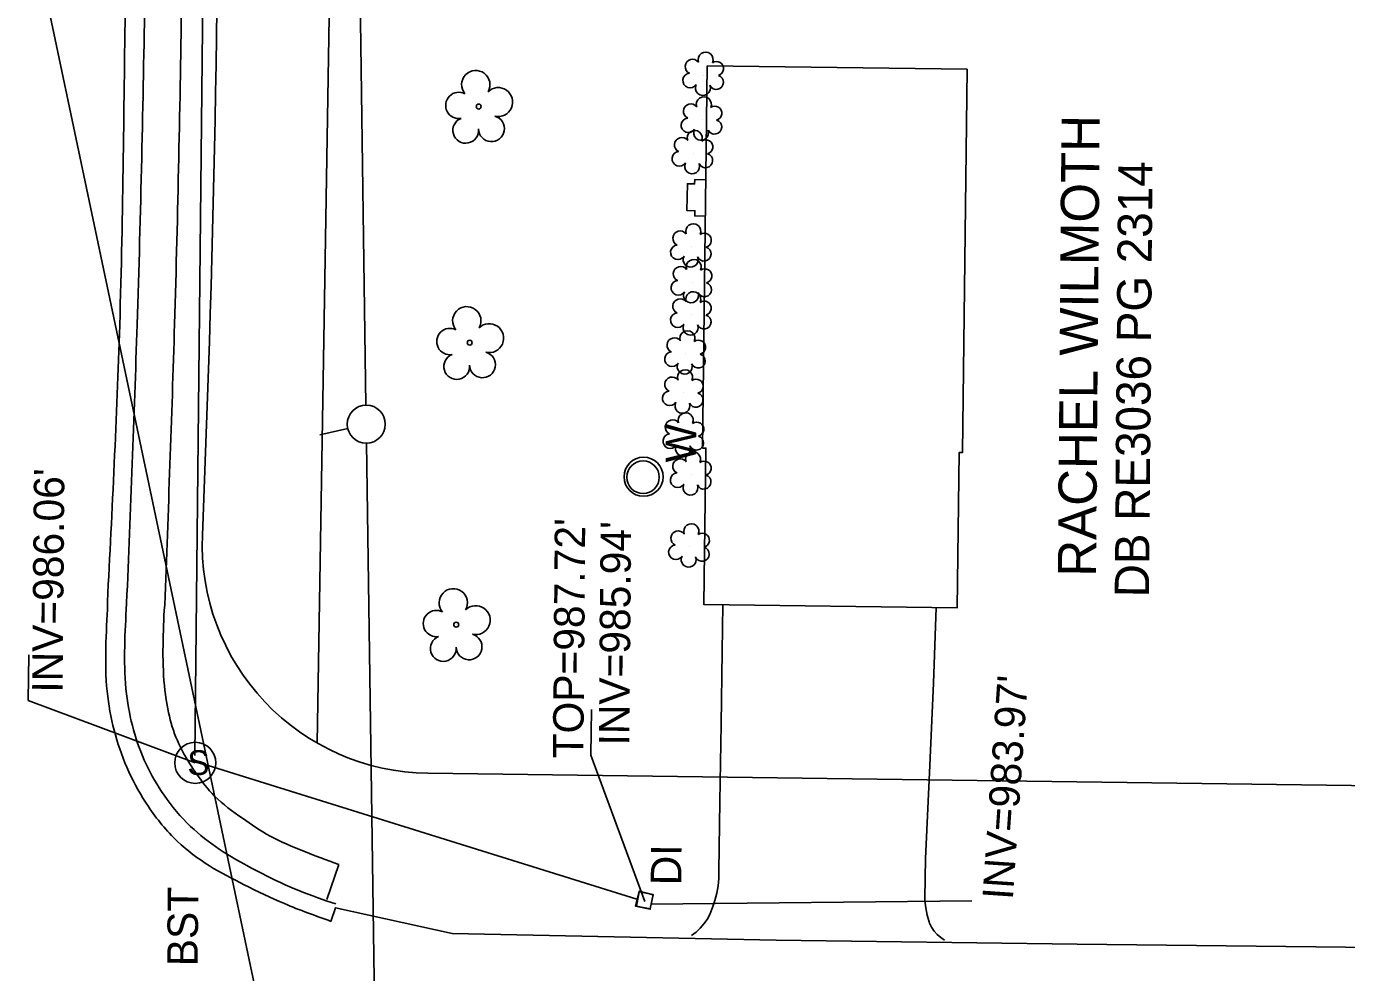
# Model space of a CAD drawing. Extents: x 1611576 to 1617186, y 899279 to 905462.
# Drawn here: x 1616695.8 to 1616869, y 902069.8 to 902193.9 of the extents above; entities that cross this region are included whole.
import ezdxf

# ---------------------------------------------------------------- set-up
doc = ezdxf.new("R2010")
doc.units = 0
for name, color, linetype in [('Default', 7, 'Continuous'), ('Exist Building', 7, 'Continuous'), ('Exist Other Culture Area Outline', 7, 'Continuous'), ('Exist Other Culture Well CELL', 7, 'Continuous'), ('Exist Other Culture Well Text', 7, 'Continuous'), ('Exist Property Deed Book Text', 7, 'Continuous'), ('Exist Property Owner Text', 7, 'Continuous'), ('Exist Right of Way Easement Line', 7, 'Continuous'), ('Exist Right of Way Line', 7, 'Continuous'), ('Exist Roads Curbs', 7, 'Continuous'), ('Exist Roads EOP', 7, 'Continuous'), ('Exist Roads EOP Other', 7, 'Continuous'), ('Exist Roads EOP Text', 7, 'Continuous'), ('Exist Structure Minor Drop Inlet', 7, 'Continuous'), ('Exist Structure Minor Drop Inlet Leader', 7, 'Continuous'), ('Exist Structure Minor Drop Inlet Text', 7, 'Continuous'), ('Exist Structure Minor Drop Inlet Top Elevation', 7, 'Continuous'), ('Exist Structure Minor Pipes RCP 12 Inch', 7, 'Continuous'), ('Exist Structure Minor Pipes RCP 12 Inch Invert', 7, 'Continuous'), ('Exist Structure Minor Pipes RCP 15 Inch', 7, 'Continuous'), ('Exist Structure Minor Pipes RCP 15 Inch Invert', 7, 'Continuous'), ('Exist Structure Minor Storm Sewer Manhole CELL', 7, 'Continuous'), ('Exist Structure Minor Storm Sewer Manhole Leader', 7, 'Continuous'), ('Exist Vegetation Shrub CELL', 7, 'Continuous'), ('Exist Vegetation Tree CELL', 7, 'Continuous'), ('Prop OH Pow Lines', 7, 'Continuous')]:
    doc.layers.add(name, color=color, linetype=linetype)

# ---------------------------------------------------------------- blocks, each defined once
blk = doc.blocks.new('EXIST STRUCTURE MINOR STORM SEWER MANHOLE')
at = {"layer": 'Exist Structure Minor Storm Sewer Manhole CELL'}
blk.add_circle((0, 0), 0.0539, dxfattribs=at)
blk.add_text('S', height=0.065, dxfattribs=at).set_placement((-0.0206, -0.032))
blk = doc.blocks.new('EXIST OTHER CULTURE WELL')
at = {"layer": 'Exist Other Culture Well CELL'}
blk.add_circle((0.0001, 0.0001), 0.0512, dxfattribs=at)

msp = doc.modelspace()

# ---------------------------------------------------------------- linework, layer by layer
at = {"layer": 'Default'}
msp.add_line((1616737.91, 902141.2), (1616734.25, 902140.36), dxfattribs=at)
msp.add_circle((1616740.35, 902141.76), 2.5, dxfattribs=at)
at = {"layer": 'Exist Building'}
msp.add_lwpolyline([(1616819.19, 902188.32), (1616818.57, 902138.04), (1616818.13, 902138.04), (1616817.88, 902117.69), (1616784.65, 902118.1), (1616784.91, 902138.63), (1616784.47, 902138.63), (1616785.09, 902188.74)], close=True, dxfattribs=at)
at = {"layer": 'Exist Other Culture Area Outline'}
msp.add_lwpolyline([(1616784.84, 902169.04), (1616783.44, 902169.08), (1616783.46, 902169.75), (1616782.41, 902169.77), (1616782.49, 902173.3), (1616783.43, 902173.28), (1616783.44, 902173.85), (1616784.9, 902173.82)], dxfattribs=at)
at = {"layer": 'Exist Other Culture Well CELL'}
msp.add_circle((1616776.73, 902134.86), 2.56, dxfattribs=at)
at = {"layer": 'Exist Right of Way Easement Line'}
msp.add_line((1616733.92, 902099.93), (1616735.65, 902205.83), dxfattribs=at)
at = {"layer": 'Exist Right of Way Line'}
for p, q in [((1616010.65, 905462.23), (1616993.32, 900797.76)), ((1616748.43, 902095.97), (1616995.9, 902092.72))]:
    msp.add_line(p, q, dxfattribs=at)
for centre, radius, start, end in [((1614235.45, 902230.14), 2485.53, 357.62671, 2.98333), ((1616748.82, 902125.97), 30, 177.6267, 269.2466)]:
    msp.add_arc(centre, radius, start, end, dxfattribs=at)
at = {"layer": 'Exist Roads Curbs'}
for p, q in [((1616708.91, 902118.28), (1616708.86, 902117.45)), ((1616735.21, 902079.21), (1616736.35, 902078.85))]:
    msp.add_line(p, q, dxfattribs=at)
for points in [[(1616711.07, 902282.06), (1616711.54, 902240.78), (1616711.3, 902198.45), (1616710.29, 902154.83), (1616708.91, 902118.28)], [(1616708.86, 902117.45), (1616708.9, 902106.37), (1616711.47, 902097.16), (1616713.82, 902093.09), (1616717.31, 902088.99), (1616721.06, 902086.03), (1616725.48, 902083.44), (1616730.31, 902081.08), (1616735.21, 902079.21)]]:
    msp.add_spline(points, degree=3, dxfattribs=at)
at = {"layer": 'Exist Roads EOP'}
msp.add_line((1616706.39, 902118.44), (1616706.4, 902117.47), dxfattribs=at)
msp.add_lwpolyline([(1616735.72, 902076.55), (1616736.31, 902078.34), (1616751.61, 902074.96), (1616794.12, 902074.08), (1616833.63, 902073.55), (1616876.66, 902073.09), (1616919.02, 902072.24), (1616961.16, 902071.7), (1616995.87, 902071.17)], dxfattribs=at)
for points in [[(1616700.66, 902435.94), (1616702.18, 902418.73), (1616703.04, 902404.79), (1616704.57, 902383.66), (1616705.67, 902361.58), (1616706.31, 902348.15), (1616707.03, 902335.33), (1616707.82, 902320.47), (1616708.2, 902308.47), (1616708.4, 902295.6), (1616708.73, 902282.72), (1616709.32, 902240.78), (1616708.76, 902198.62), (1616708, 902154.76), (1616706.39, 902118.44)], [(1616706.4, 902117.47), (1616706.43, 902106.02), (1616709.2, 902096.18), (1616711.76, 902091.62), (1616715.59, 902087.04), (1616719.77, 902083.84), (1616724.34, 902081.35), (1616729.62, 902078.87), (1616735.72, 902076.55)]]:
    msp.add_spline(points, degree=3, dxfattribs=at)
at = {"layer": 'Exist Roads EOP Other'}
for p, q in [((1616713.91, 902118.06), (1616713.83, 902117.33)), ((1616736.74, 902084), (1616735.16, 902079.4))]:
    msp.add_line(p, q, dxfattribs=at)
for points in [[(1616783.04, 902074.7), (1616783.63, 902075.14), (1616784.17, 902075.65), (1616784.65, 902076.21), (1616785.07, 902076.81), (1616785.42, 902077.46), (1616785.7, 902078.15), (1616785.77, 902078.38), (1616786.1, 902079.3), (1616786.34, 902080.25), (1616786.51, 902081.22), (1616786.6, 902082.19), (1616786.61, 902083.17), (1616786.61, 902083.19), (1616786.75, 902092.29), (1616786.9, 902102.43), (1616787.03, 902111.95), (1616787.12, 902118.07)], [(1616816.21, 902074.1), (1616815.71, 902074.43), (1616815.26, 902074.82), (1616814.86, 902075.27), (1616814.52, 902075.77), (1616814.26, 902076.31), (1616814.19, 902076.47), (1616813.93, 902077.38), (1616813.75, 902078.32), (1616813.64, 902079.26), (1616813.62, 902079.61), (1616813.74, 902084.78), (1616814.25, 902096.04), (1616814.76, 902107.81), (1616815.1, 902117.72)]]:
    msp.add_lwpolyline(points, dxfattribs=at)
for points in [[(1616716.14, 902275.65), (1616716.52, 902240.91), (1616716.15, 902198.42), (1616715.2, 902154.87), (1616713.91, 902118.06)], [(1616713.83, 902117.33), (1616713.94, 902106.82), (1616715.96, 902099.38), (1616718.02, 902095.99), (1616720.46, 902092.98), (1616724.09, 902090.07), (1616727.73, 902087.73), (1616732.03, 902085.79), (1616736.74, 902084)]]:
    msp.add_spline(points, degree=3, dxfattribs=at)
at = {"layer": 'Exist Structure Minor Drop Inlet'}
msp.add_lwpolyline([(1616777.99, 902080.01), (1616777.59, 902078.19), (1616777.61, 902078.13), (1616775.69, 902078.54), (1616776.15, 902080.49), (1616777.99, 902080.01)], dxfattribs=at)
msp.add_lwpolyline([(1616777.61, 902078.18), (1616775.81, 902078.52), (1616776.17, 902080.42), (1616777.97, 902080.08)], close=True, dxfattribs=at)
at = {"layer": 'Exist Structure Minor Drop Inlet Leader'}
msp.add_lwpolyline([(1616776.88, 902079.16), (1616769.83, 902098.35), (1616769.88, 902104.35)], dxfattribs=at)
at = {"layer": 'Exist Structure Minor Pipes RCP 12 Inch'}
msp.add_line((1616819.8, 902079.23), (1616777.68, 902078.8), dxfattribs=at)
at = {"layer": 'Exist Structure Minor Pipes RCP 15 Inch'}
for p, q in [((1616720.08, 902307.67), (1616717.86, 902098.31)), ((1616720.08, 902307.67), (1616717.86, 902098.31)), ((1616775.83, 902079.48), (1616718.9, 902097.22))]:
    msp.add_line(p, q, dxfattribs=at)
at = {"layer": 'Exist Structure Minor Storm Sewer Manhole Leader'}
msp.add_lwpolyline([(1616717.91, 902097.34), (1616696.01, 902105.52), (1616696.06, 902111.52)], dxfattribs=at)
at = {"layer": 'Exist Vegetation Shrub CELL'}
for p, q in [((1616784.64, 902187.53), (1616784.64, 902187.53)), ((1616784.41, 902181.67), (1616784.41, 902181.67)), ((1616783.22, 902177.26), (1616783.22, 902177.26)), ((1616783.03, 902165.01), (1616783.03, 902165.01)), ((1616783.09, 902160.34), (1616783.09, 902160.34)), ((1616783.02, 902156.11), (1616783.02, 902156.11)), ((1616782.26, 902150.99), (1616782.26, 902150.99)), ((1616781.96, 902145.86), (1616781.96, 902145.86)), ((1616782.03, 902140.23), (1616782.03, 902140.23)), ((1616783, 902135.11), (1616783, 902135.11)), ((1616782.77, 902125.66), (1616782.77, 902125.66))]:
    msp.add_line(p, q, dxfattribs=at)
for centre, radius, start, end in [((1616784.87, 902189.57), 0.99, 334.8391, 200.4717), ((1616783.16, 902188.66), 0.968, 35.8908, 245.4216), ((1616786.31, 902188.4), 0.929, 284.4567, 126.0861), ((1616782.84, 902186.83), 0.955, 95.1099, 327.9534), ((1616786.28, 902186.6), 0.937, 204.9913, 73.4601), ((1616784.51, 902185.85), 0.984, 151.2797, 21.387), ((1616782.93, 902182.8), 0.968, 35.8908, 245.4216), ((1616784.64, 902183.71), 0.99, 334.8391, 200.4717), ((1616786.08, 902182.54), 0.929, 284.4567, 126.0861), ((1616782.61, 902180.96), 0.955, 95.1099, 327.9534), ((1616783.45, 902179.3), 0.99, 334.8391, 200.4717), ((1616784.28, 902179.98), 0.984, 151.2797, 21.387), ((1616786.05, 902180.74), 0.937, 204.9913, 73.4601), ((1616781.74, 902178.39), 0.968, 35.8908, 245.4216), ((1616784.9, 902178.13), 0.929, 284.4567, 126.0861), ((1616781.42, 902176.56), 0.955, 95.1099, 327.9534), ((1616784.86, 902176.33), 0.937, 204.9913, 73.4601), ((1616783.1, 902175.58), 0.984, 151.2797, 21.387), ((1616783.25, 902167.06), 0.99, 334.8391, 200.4717), ((1616781.54, 902166.14), 0.968, 35.8908, 245.4216), ((1616784.7, 902165.88), 0.929, 284.4567, 126.0861), ((1616781.23, 902164.31), 0.955, 95.1099, 327.9534), ((1616784.66, 902164.09), 0.937, 204.9913, 73.4601), ((1616782.9, 902163.33), 0.984, 151.2797, 21.387), ((1616783.32, 902162.38), 0.99, 334.8391, 200.4717), ((1616781.6, 902161.47), 0.968, 35.8908, 245.4216), ((1616784.76, 902161.21), 0.929, 284.4567, 126.0861), ((1616781.29, 902159.64), 0.955, 95.1099, 327.9534), ((1616784.72, 902159.41), 0.937, 204.9913, 73.4601), ((1616781.53, 902157.23), 0.968, 35.8908, 245.4216), ((1616782.96, 902158.66), 0.984, 151.2797, 21.387), ((1616783.25, 902158.15), 0.99, 334.8391, 200.4717), ((1616784.69, 902156.98), 0.929, 284.4567, 126.0861), ((1616781.22, 902155.4), 0.955, 95.1099, 327.9534), ((1616784.65, 902155.18), 0.937, 204.9913, 73.4601), ((1616782.48, 902153.03), 0.99, 334.8391, 200.4717), ((1616782.89, 902154.42), 0.984, 151.2797, 21.387), ((1616780.77, 902152.11), 0.968, 35.8908, 245.4216), ((1616783.93, 902151.85), 0.929, 284.4567, 126.0861), ((1616780.46, 902150.28), 0.955, 95.1099, 327.9534), ((1616783.89, 902150.06), 0.937, 204.9913, 73.4601), ((1616782.13, 902149.3), 0.984, 151.2797, 21.387), ((1616782.18, 902147.9), 0.99, 334.8391, 200.4717), ((1616780.47, 902146.98), 0.968, 35.8908, 245.4216), ((1616783.63, 902146.73), 0.929, 284.4567, 126.0861), ((1616780.16, 902145.15), 0.955, 95.1099, 327.9534), ((1616783.59, 902144.93), 0.937, 204.9913, 73.4601), ((1616781.83, 902144.17), 0.984, 151.2797, 21.387), ((1616780.55, 902141.36), 0.968, 35.8908, 245.4216), ((1616782.26, 902142.27), 0.99, 334.8391, 200.4717), ((1616783.7, 902141.1), 0.929, 284.4567, 126.0861), ((1616780.23, 902139.53), 0.955, 95.1099, 327.9534), ((1616783.66, 902139.3), 0.937, 204.9913, 73.4601), ((1616781.9, 902138.55), 0.984, 151.2797, 21.387), ((1616781.52, 902136.24), 0.968, 35.8908, 245.4216), ((1616783.23, 902137.15), 0.99, 334.8391, 200.4717), ((1616784.68, 902135.98), 0.929, 284.4567, 126.0861), ((1616781.2, 902134.41), 0.955, 95.1099, 327.9534), ((1616784.64, 902134.18), 0.937, 204.9913, 73.4601), ((1616782.88, 902133.43), 0.984, 151.2797, 21.387), ((1616783, 902127.7), 0.99, 334.8391, 200.4717), ((1616781.29, 902126.79), 0.968, 35.8908, 245.4216), ((1616784.44, 902126.53), 0.929, 284.4567, 126.0861), ((1616780.97, 902124.96), 0.955, 95.1099, 327.9534), ((1616784.41, 902124.73), 0.937, 204.9913, 73.4601), ((1616782.64, 902123.98), 0.984, 151.2797, 21.387)]:
    msp.add_arc(centre, radius, start, end, dxfattribs=at)
at = {"layer": 'Exist Vegetation Tree CELL'}
for p, q in [((1616755.1, 902183.42), (1616755.1, 902183.42)), ((1616753.92, 902152.45), (1616753.92, 902152.45)), ((1616752.16, 902115.46), (1616752.16, 902115.46))]:
    msp.add_line(p, q, dxfattribs=at)
for centre in [(1616755.1, 902183.42), (1616753.92, 902152.45), (1616752.16, 902115.46)]:
    msp.add_circle(centre, 0.326, dxfattribs=at)
for centre, radius, start, end in [((1616754.72, 902186.29), 1.86, 330.1651, 219.7134), ((1616752.5, 902183.57), 1.73, 62.6636, 279.3457), ((1616757.65, 902184.01), 1.9, 257.1011, 134.1999), ((1616753.4, 902180.3), 1.69, 111.5671, 6.231), ((1616756.78, 902180.52), 1.7, 181.2822, 74.56), ((1616753.54, 902155.32), 1.86, 330.1651, 219.7134), ((1616751.32, 902152.6), 1.73, 62.6636, 279.3457), ((1616756.47, 902153.04), 1.9, 257.1011, 134.1999), ((1616752.22, 902149.33), 1.69, 111.5671, 6.231), ((1616755.6, 902149.55), 1.7, 181.2822, 74.56), ((1616751.77, 902118.33), 1.86, 330.1651, 219.7134), ((1616754.71, 902116.05), 1.9, 257.1011, 134.1999), ((1616749.55, 902115.61), 1.73, 62.6636, 279.3457), ((1616753.83, 902112.56), 1.7, 181.2822, 74.56), ((1616750.45, 902112.34), 1.69, 111.5671, 6.231)]:
    msp.add_arc(centre, radius, start, end, dxfattribs=at)
at = {"layer": 'Prop OH Pow Lines'}
for p, q in [((1616740.31, 902144.25), (1616739.21, 902220.85)), ((1616742.01, 902026.11), (1616740.38, 902139.26))]:
    msp.add_line(p, q, dxfattribs=at)

# ---------------------------------------------------------------- block references
at = {"layer": 'Exist Other Culture Well CELL', "xscale": 41.66666666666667, "yscale": 41.66666666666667}
msp.add_blockref('EXIST OTHER CULTURE WELL', (1616776.66, 902134.8), dxfattribs=at)
at = {"layer": 'Exist Structure Minor Storm Sewer Manhole CELL', "xscale": 50, "yscale": 50}
msp.add_blockref('EXIST STRUCTURE MINOR STORM SEWER MANHOLE', (1616717.91, 902097.34), dxfattribs=at)

# ---------------------------------------------------------------- texts
at = {"layer": 'Exist Other Culture Well Text'}
msp.add_text('W', height=4, rotation=89.5333, dxfattribs=at).set_placement((1616783.62, 902136.71))
at = {"layer": 'Exist Property Deed Book Text'}
msp.add_text('DB RE3036 PG 2314', height=4.5, rotation=89.5333, dxfattribs=at).set_placement((1616843.04, 902119.04))
at = {"layer": 'Exist Property Owner Text'}
msp.add_text('RACHEL WILMOTH', height=5, rotation=89.5333, dxfattribs=at).set_placement((1616836.08, 902121.74))
at = {"layer": 'Exist Roads EOP Text'}
msp.add_text('BST', height=4, rotation=89.5333, dxfattribs=at).set_placement((1616718.23, 902070.65))
at = {"layer": 'Exist Structure Minor Drop Inlet Text'}
msp.add_text('DI', height=4, rotation=89.5333, dxfattribs=at).set_placement((1616781.67, 902081.27))
at = {"layer": 'Exist Structure Minor Drop Inlet Top Elevation'}
msp.add_text("TOP=987.72'", height=4, rotation=89.5333, dxfattribs=at).set_placement((1616768.83, 902097.91))
at = {"layer": 'Exist Structure Minor Pipes RCP 12 Inch Invert'}
for s, rotation, p in [("INV=985.94'", 89.5333, (1616774.86, 902099.6)), ("INV=983.97'", 86.0833, (1616825.17, 902079.31))]:
    msp.add_text(s, height=4, rotation=rotation, dxfattribs=at).set_placement(p)
at = {"layer": 'Exist Structure Minor Pipes RCP 15 Inch Invert'}
msp.add_text("INV=986.06'", height=4, rotation=89.5333, dxfattribs=at).set_placement((1616700.51, 902106.53))

doc.saveas('drawing.dxf')
